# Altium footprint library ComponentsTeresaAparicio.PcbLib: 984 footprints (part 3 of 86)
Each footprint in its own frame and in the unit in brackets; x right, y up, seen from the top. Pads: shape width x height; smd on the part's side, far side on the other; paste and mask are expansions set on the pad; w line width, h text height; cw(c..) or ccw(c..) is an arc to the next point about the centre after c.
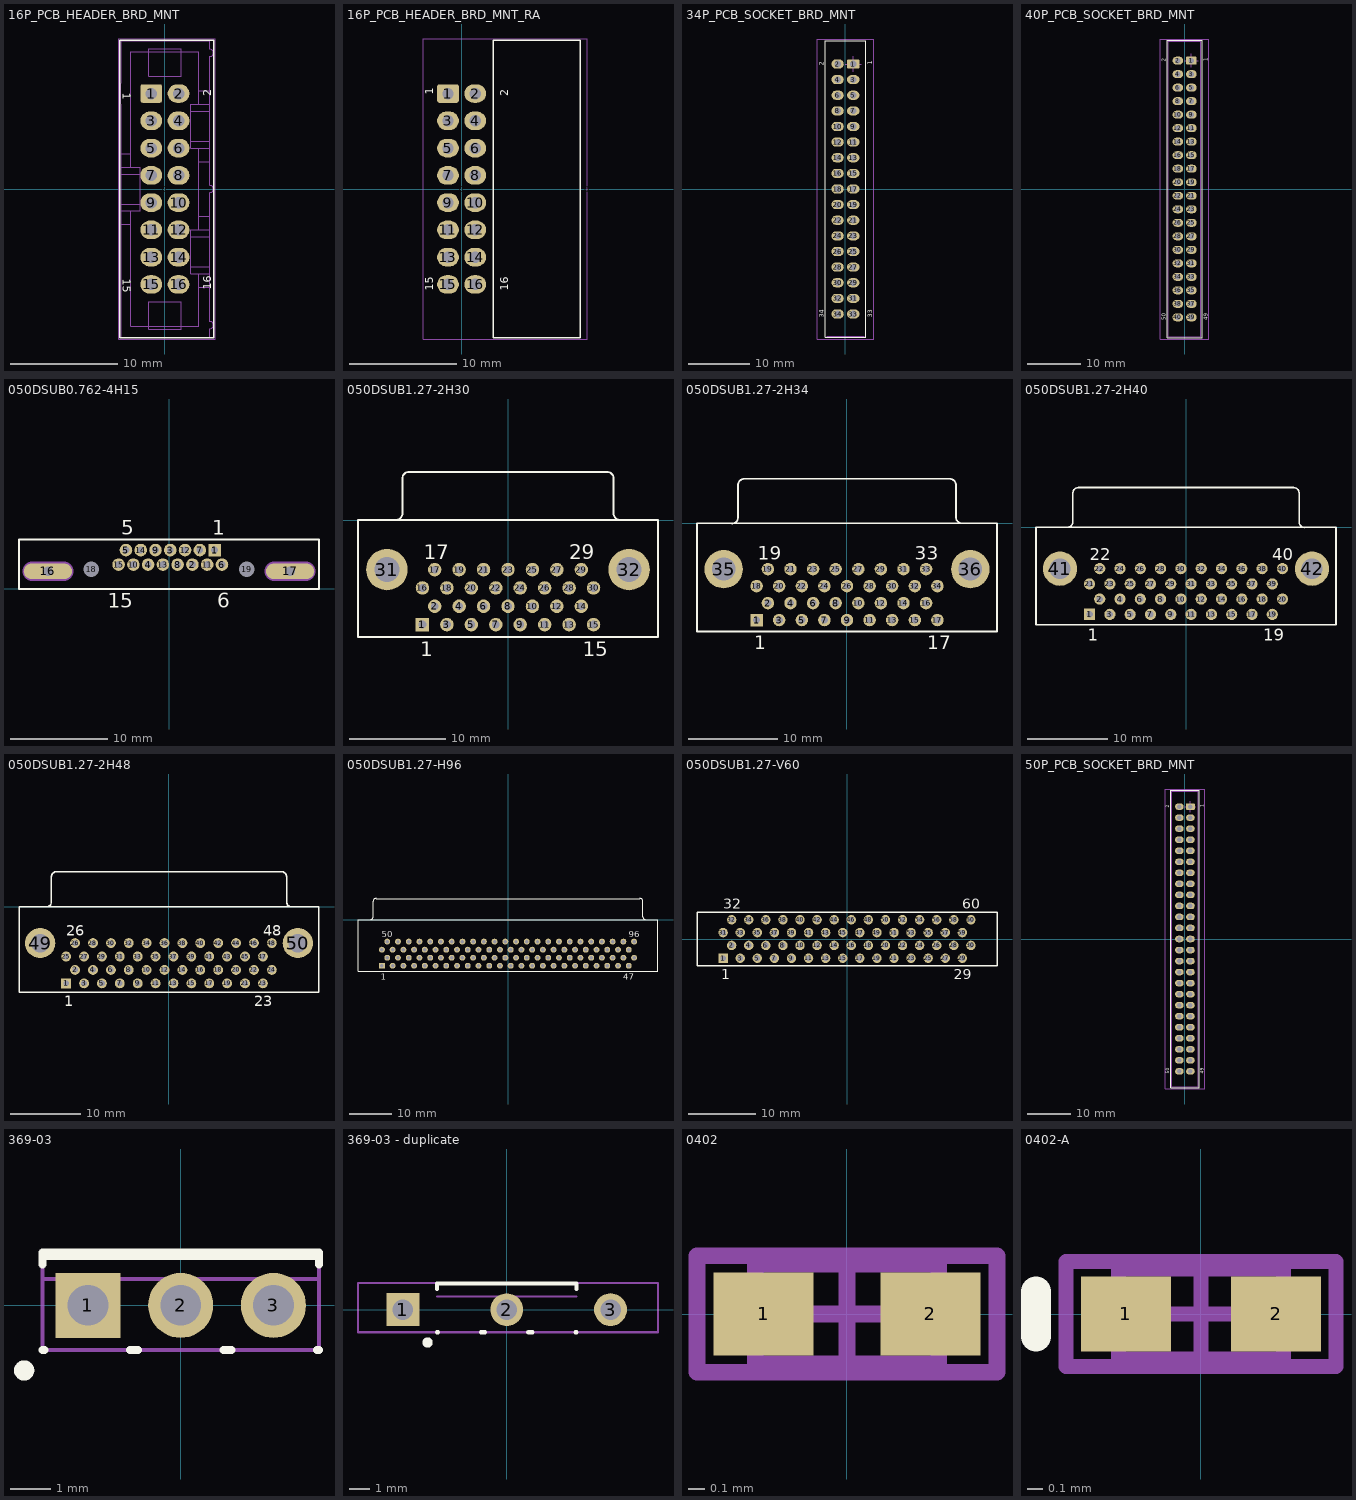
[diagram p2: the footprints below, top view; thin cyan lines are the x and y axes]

## 16P_PCB_HEADER_BRD_MNT [mil] "HEADER BRD MNT 16POS 2.54MM"
height 390
pads (17):
  round 40 on Mech14: 0(0,0)
  rrect25% 80x68 hole 42: 1(-50,350)
  oval 80x68 hole 42: 2(50,350) 3(-50,250) 4(50,250) 5(-50,150) 6(50,150) 7(-50,50) 8(50,50) 9(-50,-50) 10(50,-50) 11(-50,-150) 12(50,-150) 13(-50,-250) 14(50,-250) 15(-50,-350) 16(50,-350)
Top Overlay:
  lines w5: -165,-545 -165,545 180,545 180,-545 -165,-545
  text "2" at 170,340 h30
  text "1" at -155,353.57 h30
  text "16" at 170,-370.28 h30
  text "15" at -155,-329 h30
Mechanical 13:
  drawing of 242 lines, arcs and shapes, not listed
Mechanical 14:
  lines w3: -170,-550 -170,550 185,550 185,-550 -170,-550
3D body: height 390, standoff -120, extent -161.99,-543.99 178.01,544.01

## 16P_PCB_HEADER_BRD_MNT_RA [mil] "HEADER BRD MNT R/A 16POS 2.54MM"
height 338
pads (18):
  round 40 on Mech14: 0(0,0) 0(460,0)
  rrect25% 80x68 hole 42: 1(-50,350)
  oval 80x68 hole 42: 2(50,350) 3(-50,250) 4(50,250) 5(-50,150) 6(50,150) 7(-50,50) 8(50,50) 9(-50,-50) 10(50,-50) 11(-50,-150) 12(50,-150) 13(-50,-250) 14(50,-250) 15(-50,-350) 16(50,-350)
Top Overlay:
  lines w5: 115,-545 435,-545 435,545 115,545 115,-545
  text "15" at -105,-373 h30
  text "16" at 170,-373 h30
  text "1" at -105,345 h30
  text "2" at 170,340 h30
Mechanical 14:
  lines w3: -140,-550 460,-550 460,550 -140,550 -140,-550
3D body: height 340, standoff -112, extent -62.24,-543.99 440.01,544.01

## 34P_PCB_SOCKET_BRD_MNT [mm] "SOCKET BRD MNT 34POS 2.54MM"
height 10.8
pads (34):
  rrect25% 2x1.5 hole 1.067: 1(1.27,20.32)
  oval 2x1.5 hole 1.067: 2(-1.27,20.32) 3(1.27,17.78) 4(-1.27,17.78) 5(1.27,15.24) 6(-1.27,15.24) 7(1.27,12.7) 8(-1.27,12.7) 9(1.27,10.16) 10(-1.27,10.16) 11(1.27,7.62) 12(-1.27,7.62) 13(1.27,5.08) 14(-1.27,5.08) 15(1.27,2.54) 16(-1.27,2.54) 17(1.27,0) 18(-1.27,0) 19(1.27,-2.54) 20(-1.27,-2.54) 21(1.27,-5.08) 22(-1.27,-5.08) 23(1.27,-7.62) 24(-1.27,-7.62) 25(1.27,-10.16) 26(-1.27,-10.16) 27(1.27,-12.7) 28(-1.27,-12.7) 29(1.27,-15.24) 30(-1.27,-15.24) 31(1.27,-17.78) 32(-1.27,-17.78) 33(1.27,-20.32) 34(-1.27,-20.32)
Top Overlay:
  lines w0.127: -3.302,-24.13 -3.302,24.13 3.302,24.13 3.302,-24.13 -3.302,-24.13
  text "1" at 4.318,20.193 h0.76
  text "2" at -3.556,20.066 h0.76
  text "33" at 4.318,-20.904 h0.76
  text "34" at -3.556,-20.904 h0.76
Mechanical 13:
  lines w0.076: -3.05,-23.92 3.05,-23.92
Mechanical 14:
  lines w0.076: 0,20.32 2.54,20.32 ; 1.27,19.05 1.27,21.59 ; -4.572,-24.384 -4.572,24.384 4.572,24.384 4.572,-24.384 -4.572,-24.384
3D body: height 10.8, standoff -2.8, extent -3.05,-23.925 4.05,23.915

## 40P_PCB_SOCKET_BRD_MNT [mm] "SOCKET BRD MNT 40POS 2.54MM"
height 10.8
pads (40):
  rrect25% 2x1.5 hole 1.067: 1(1.27,24.13)
  oval 2x1.5 hole 1.067: 2(-1.27,24.13) 3(1.27,21.59) 4(-1.27,21.59) 5(1.27,19.05) 6(-1.27,19.05) 7(1.27,16.51) 8(-1.27,16.51) 9(1.27,13.97) 10(-1.27,13.97) 11(1.27,11.43) 12(-1.27,11.43) 13(1.27,8.89) 14(-1.27,8.89) 15(1.27,6.35) 16(-1.27,6.35) 17(1.27,3.81) 18(-1.27,3.81) 19(1.27,1.27) 20(-1.27,1.27) 21(1.27,-1.27) 22(-1.27,-1.27) 23(1.27,-3.81) 24(-1.27,-3.81) 25(1.27,-6.35) 26(-1.27,-6.35) 27(1.27,-8.89) 28(-1.27,-8.89) 29(1.27,-11.43) 30(-1.27,-11.43) 31(1.27,-13.97) 32(-1.27,-13.97) 33(1.27,-16.51) 34(-1.27,-16.51) 35(1.27,-19.05) 36(-1.27,-19.05) 37(1.27,-21.59) 38(-1.27,-21.59) 39(1.27,-24.13) 40(-1.27,-24.13)
Top Overlay:
  lines w0.127: -3.302,-27.94 -3.302,27.94 3.302,27.94 3.302,-27.94 -3.302,-27.94
  text "50" at -3.556,-24.714 h0.76
  text "49" at 4.318,-24.714 h0.76
  text "2" at -3.556,23.876 h0.76
  text "1" at 4.318,24.003 h0.76
Mechanical 13:
  lines w0.076: -3.05,-27.73 3.05,-27.73 3.05,27.73 -3.05,27.73 -3.05,-27.73
Mechanical 14:
  lines w0.076: 0,24.13 2.54,24.13 ; 1.27,22.86 1.27,25.4 ; -4.572,-28.194 -4.572,28.194 4.572,28.194 4.572,-28.194 -4.572,-28.194
3D body: height 10.8, standoff -2.54, extent -3.05,-27.73 4.05,27.73

## 050DSUB0.762-4H15 [mm] "Connector; D Subminiature; 15 Position; Right Angle; Pitch 0.762 mm"
height 12.65
pads (19):
  rect 1.3x1.3 hole 0.7: 1(4.703,4)
  round 1.3 hole 0.7: 2(2.417,2.5) 3(0.131,4) 4(-2.155,2.5) 5(-4.441,4) 6(5.465,2.5) 7(3.179,4) 8(0.893,2.5) 9(-1.393,4) 10(-3.679,2.5) 11(3.941,2.5) 12(1.655,4) 13(-0.631,2.5) 14(-2.917,4) 15(-5.203,2.5)
  oval 5x1.6 hole 1: 16(-12.495,1.8) 17(12.495,1.8)
  round 1.3 hole 1.6: 18(-8,2) 19(8,2)
Top Overlay:
  lines w0.2: -15.48,0 15.48,0 15.48,5.1 -15.48,5.1 -15.48,0
  text "15" at -6.328,-1.975 h1.5
  text "6" at 4.965,-1.975 h1.5
  text "1" at 4.453,5.6 h1.5
  text "5" at -4.941,5.6 h1.5
Mechanical 1:
  lines w1.2: -14.12,1.8 -10.87,1.8 ; 10.87,1.8 14.12,1.8
  text "Alert PCB fab to slot details" at -15.505,-1.17 h0.3
  text "Slot 1.2x4.45mm, PTH" at -15.505,-1.67 h0.3
  text "Assign keep-out area to slot" at -15.505,-0.67 h0.3
  text "Mech 1 - Slot cut-out" at -15.505,-2.17 h0.3
  text "Mech 2 - Clearance, move to internal plane if present" at -15.505,-2.67 h0.3
Mechanical 2:
  lines w2.016: -14.12,1.8 -10.87,1.8 ; 10.87,1.8 14.12,1.8

## 050DSUB1.27-2H30 [mm] "Connector; D Subminiature; 30 Position; Right Angle; Pitch 1.27 mm"
height 8.1
pads (32):
  rect 1.4x1.4 hole 0.8: 1(-8.89,-10.87)
  round 1.4 hole 0.8: 2(-7.62,-8.965) 3(-6.35,-10.87) 4(-5.08,-8.965) 5(-3.81,-10.87) 6(-2.54,-8.965) 7(-1.27,-10.87) 8(0,-8.965) 9(1.27,-10.87) 10(2.54,-8.965) 11(3.81,-10.87) 12(5.08,-8.965) 13(6.35,-10.87) 14(7.62,-8.965) 15(8.89,-10.87) 16(-8.89,-7.06) 17(-7.62,-5.155) 18(-6.35,-7.06) 19(-5.08,-5.155) 20(-3.81,-7.06) 21(-2.54,-5.155) 22(-1.27,-7.06) 23(0,-5.155) 24(1.27,-7.06) 25(2.54,-5.155) 26(3.81,-7.06) 27(5.08,-5.155) 28(6.35,-7.06) 29(7.62,-5.155) 30(8.89,-7.06)
  round 4.3 hole 2.6: 31(-12.59,-5.155) 32(12.59,-5.155)
Top Overlay:
  lines w0.2: -11.67,0 ccw(c-11.67,0.695) -10.975,0.695 ; -10.975,0.715 -10.975,4.305 cw(c-10.28,4.305) -10.28,5 10.28,5 cw(c10.28,4.305) 10.975,4.305 ; 10.975,4.495 10.975,0.695 ccw(c11.67,0.695) 11.67,0 ; -15.59,-12.17 -15.59,0 15.59,0 15.59,-12.17 -15.59,-12.17
  text "17" at -8.745,-4.08 h1.5
  text "29" at 6.37,-4.08 h1.5
  text "1" at -9.14,-14.145 h1.5
  text "15" at 7.765,-14.145 h1.5

## 050DSUB1.27-2H34 [mm] "Connector; D Subminiature; 34 Position; Right Angle; Pitch 1.27 mm"
height 7.6
pads (36):
  rect 1.4x1.4 hole 0.8: 1(-10.16,-10.87)
  round 1.4 hole 0.8: 2(-8.89,-8.965) 3(-7.62,-10.87) 4(-6.35,-8.965) 5(-5.08,-10.87) 6(-3.81,-8.965) 7(-2.54,-10.87) 8(-1.27,-8.965) 9(0,-10.87) 10(1.27,-8.965) 11(2.54,-10.87) 12(3.81,-8.965) 13(5.08,-10.87) 14(6.35,-8.965) 15(7.62,-10.87) 16(8.89,-8.965) 17(10.16,-10.87) 18(-10.16,-7.06) 19(-8.89,-5.155) 20(-7.62,-7.06) 21(-6.35,-5.155) 22(-5.08,-7.06) 23(-3.81,-5.155) 24(-2.54,-7.06) 25(-1.27,-5.155) 26(0,-7.06) 27(1.27,-5.155) 28(2.54,-7.06) 29(3.81,-5.155) 30(5.08,-7.06) 31(6.35,-5.155) 32(7.62,-7.06) 33(8.89,-5.155) 34(10.16,-7.06)
  round 4.3 hole 2.6: 35(-13.86,-5.155) 36(13.86,-5.155)
Top Overlay:
  lines w0.2: -12.94,-0.02 ccw(c-12.94,0.675) -12.245,0.675 -12.245,4.305 cw(c-11.55,4.305) -11.55,5 11.5,5 ; 11.55,5 cw(c11.55,4.305) 12.245,4.305 12.245,0.695 ccw(c12.94,0.695) 12.94,0 ; -16.86,-12.17 16.86,-12.17 16.86,0 -16.86,0 -16.86,-12.17
  text "19" at -10.015,-4.08 h1.5
  text "33" at 7.64,-4.08 h1.5
  text "1" at -10.41,-14.145 h1.5
  text "17" at 9.035,-14.145 h1.5

## 050DSUB1.27-2H40 [mm] "Connector; D Subminiature; 40 Position; Right Angle; Pitch 1.27 mm"
height 8.1
pads (42):
  rect 1.4x1.4 hole 0.8: 1(-12.065,-10.87)
  round 1.4 hole 0.8: 2(-10.795,-8.965) 3(-9.525,-10.87) 4(-8.255,-8.965) 5(-6.985,-10.87) 6(-5.715,-8.965) 7(-4.445,-10.87) 8(-3.175,-8.965) 9(-1.905,-10.87) 10(-0.635,-8.965) 11(0.635,-10.87) 12(1.905,-8.965) 13(3.175,-10.87) 14(4.445,-8.965) 15(5.715,-10.87) 16(6.985,-8.965) 17(8.255,-10.87) 18(9.525,-8.965) 19(10.795,-10.87) 20(12.065,-8.965) 21(-12.065,-7.06) 22(-10.795,-5.155) 23(-9.525,-7.06) 24(-8.255,-5.155) 25(-6.985,-7.06) 26(-5.715,-5.155) 27(-4.445,-7.06) 28(-3.175,-5.155) 29(-1.905,-7.06) 30(-0.635,-5.155) 31(0.635,-7.06) 32(1.905,-5.155) 33(3.175,-7.06) 34(4.445,-5.155) 35(5.715,-7.06) 36(6.985,-5.155) 37(8.255,-7.06) 38(9.525,-5.155) 39(10.795,-7.06) 40(12.065,-5.155)
  round 4.3 hole 2.6: 41(-15.765,-5.155) 42(15.765,-5.155)
Top Overlay:
  lines w0.2: -14.845,0.02 ccw(c-14.845,0.715) -14.15,0.715 -14.15,4.305 cw(c-13.455,4.305) -13.455,5 ; -13.5,5 13.5,5 ; 13.455,5 cw(c13.455,4.305) 14.15,4.305 14.15,0.687 ccw(c14.845,0.687) 14.845,-0.008 ; -18.765,-12.17 -18.765,0 18.765,0 18.765,-12.17 -18.765,-12.17
  text "19" at 9.67,-14.145 h1.5
  text "1" at -12.315,-14.145 h1.5
  text "22" at -12.045,-4.08 h1.5
  text "40" at 10.815,-4.08 h1.5

## 050DSUB1.27-2H48 [mm] "Connector; D Subminiature; 48 Position; Right Angle; Pitch 1.27 mm"
height 7.6
pads (50):
  rect 1.4x1.4 hole 0.8: 1(-14.605,-10.87)
  round 1.4 hole 0.8: 2(-13.335,-8.965) 3(-12.065,-10.87) 4(-10.795,-8.965) 5(-9.525,-10.87) 6(-8.255,-8.965) 7(-6.985,-10.87) 8(-5.715,-8.965) 9(-4.445,-10.87) 10(-3.175,-8.965) 11(-1.905,-10.87) 12(-0.635,-8.965) 13(0.635,-10.87) 14(1.905,-8.965) 15(3.175,-10.87) 16(4.445,-8.965) 17(5.715,-10.87) 18(6.985,-8.965) 19(8.255,-10.87) 20(9.525,-8.965) 21(10.795,-10.87) 22(12.065,-8.965) 23(13.335,-10.87) 24(14.605,-8.965) 25(-14.605,-7.06) 26(-13.335,-5.155) 27(-12.065,-7.06) 28(-10.795,-5.155) 29(-9.525,-7.06) 30(-8.255,-5.155) 31(-6.985,-7.06) 32(-5.715,-5.155) 33(-4.445,-7.06) 34(-3.175,-5.155) 35(-1.905,-7.06) 36(-0.635,-5.155) 37(0.635,-7.06) 38(1.905,-5.155) 39(3.175,-7.06) 40(4.445,-5.155) 41(5.715,-7.06) 42(6.985,-5.155) 43(8.255,-7.06) 44(9.525,-5.155) 45(10.795,-7.06) 46(12.065,-5.155) 47(13.335,-7.06) 48(14.605,-5.155)
  round 4.3 hole 2.6: 49(-18.305,-5.155) 50(18.305,-5.155)
Top Overlay:
  lines w0.2: -17.385,0.002 ccw(c-17.385,0.697) -16.69,0.697 -16.69,4.305 cw(c-15.995,4.305) -15.995,5 ; -16,5 16,5 ; 15.995,5 cw(c15.995,4.305) 16.69,4.305 16.69,0.717 ccw(c17.385,0.717) 17.385,0.022 ; -21.305,-12.17 21.305,-12.17 21.305,0 -21.305,0 -21.305,-12.17
  text "26" at -14.585,-4.08 h1.5
  text "48" at 13.355,-4.08 h1.5
  text "1" at -14.855,-14.145 h1.5
  text "23" at 12.085,-14.145 h1.5

## 050DSUB1.27-H96 [mm] "Connector; D Subminiature; 96 Position; Right Angle; Pitch 1.27 mm"
height 7.5
pads (96):
  rect 1.4x1.4 hole 0.8: 1(-29.845,-10.915)
  round 1.4 hole 0.8: 2(-28.575,-9.01) 3(-27.305,-10.915) 4(-26.035,-9.01) 5(-24.765,-10.915) 6(-23.495,-9.01) 7(-22.225,-10.915) 8(-20.955,-9.01) 9(-19.685,-10.915) 10(-18.415,-9.01) 11(-17.145,-10.915) 12(-15.875,-9.01) 13(-14.605,-10.915) 14(-13.335,-9.01) 15(-12.065,-10.915) 16(-10.795,-9.01) 17(-9.525,-10.915) 18(-8.255,-9.01) 19(-6.985,-10.915) 20(-5.715,-9.01) 21(-4.445,-10.915) 22(-3.175,-9.01) 23(-1.905,-10.915) 24(-0.635,-9.01) 25(0.635,-10.915) 26(1.905,-9.01) 27(3.175,-10.915) 28(4.445,-9.01) 29(5.715,-10.915) 30(6.985,-9.01) 31(8.255,-10.915) 32(9.525,-9.01) 33(10.795,-10.915) 34(12.065,-9.01) 35(13.335,-10.915) 36(14.605,-9.01) 37(15.875,-10.915) 38(17.145,-9.01) 39(18.415,-10.915) 40(19.685,-9.01) 41(20.955,-10.915) 42(22.225,-9.01) 43(23.495,-10.915) 44(24.765,-9.01) 45(26.035,-10.915) 46(27.305,-9.01) 47(28.575,-10.915) 48(29.845,-9.01) 49(-29.845,-7.105) 50(-28.575,-5.2) 51(-27.305,-7.105) 52(-26.035,-5.2) 53(-24.765,-7.105) 54(-23.495,-5.2) 55(-22.225,-7.105) 56(-20.955,-5.2) 57(-19.685,-7.105) 58(-18.415,-5.2) 59(-17.145,-7.105) 60(-15.875,-5.2) 61(-14.605,-7.105) 62(-13.335,-5.2) 63(-12.065,-7.105) 64(-10.795,-5.2) 65(-9.525,-7.105) 66(-8.255,-5.2) 67(-6.985,-7.105) 68(-5.715,-5.2) 69(-4.445,-7.105) 70(-3.175,-5.2) 71(-1.905,-7.105) 72(-0.635,-5.2) 73(0.635,-7.105) 74(1.905,-5.2) 75(3.175,-7.105) 76(4.445,-5.2) 77(5.715,-7.105) 78(6.985,-5.2) 79(8.255,-7.105) 80(9.525,-5.2) 81(10.795,-7.105) 82(12.065,-5.2) 83(13.335,-7.105) 84(14.605,-5.2) 85(15.875,-7.105) 86(17.145,-5.2) 87(18.415,-7.105) 88(19.685,-5.2) 89(20.955,-7.105) 90(22.225,-5.2) 91(23.495,-7.105) 92(24.765,-5.2) 93(26.035,-7.105) 94(27.305,-5.2) 95(28.575,-7.105) 96(29.845,-5.2)
Top Overlay:
  lines w0.2: -32.625,0.005 ccw(c-32.625,0.7) -31.93,0.7 -31.93,4.33 cw(c-31.235,4.33) -31.235,5.025 ; -31.235,5 31.235,5 ; 31.235,5.025 cw(c31.235,4.33) 31.93,4.33 31.93,0.7 ccw(c32.625,0.7) 32.625,0.005 ; -35.5,-12.2 -35.5,0 35.5,0 35.5,-12.2 -35.5,-12.2
  text "96" at 28.595,-4.125 h1.5
  text "50" at -29.825,-4.125 h1.5
  text "1" at -30.095,-14.175 h1.5
  text "47" at 27.325,-14.175 h1.5

## 050DSUB1.27-V60 [mm] "Connector; D Subminiature; 60 Position; Vertical; Pitch 1.27 mm"
height 8
pads (60):
  rect 1.4x1.4 hole 0.8: 1(-18.415,-2.857)
  round 1.4 hole 0.8: 2(-17.145,-0.953) 3(-15.875,-2.857) 4(-14.605,-0.953) 5(-13.335,-2.857) 6(-12.065,-0.953) 7(-10.795,-2.857) 8(-9.525,-0.953) 9(-8.255,-2.857) 10(-6.985,-0.953) 11(-5.715,-2.857) 12(-4.445,-0.953) 13(-3.175,-2.857) 14(-1.905,-0.953) 15(-0.635,-2.857) 16(0.635,-0.953) 17(1.905,-2.857) 18(3.175,-0.953) 19(4.445,-2.857) 20(5.715,-0.953) 21(6.985,-2.857) 22(8.255,-0.953) 23(9.525,-2.857) 24(10.795,-0.953) 25(12.065,-2.857) 26(13.335,-0.953) 27(14.605,-2.857) 28(15.875,-0.953) 29(17.145,-2.857) 30(18.415,-0.953) 31(-18.415,0.953) 32(-17.145,2.857) 33(-15.875,0.953) 34(-14.605,2.857) 35(-13.335,0.953) 36(-12.065,2.857) 37(-10.795,0.953) 38(-9.525,2.857) 39(-8.255,0.953) 40(-6.985,2.857) 41(-5.715,0.953) 42(-4.445,2.857) 43(-3.175,0.953) 44(-1.905,2.857) 45(-0.635,0.953) 46(0.635,2.857) 47(1.905,0.953) 48(3.175,2.857) 49(4.445,0.953) 50(5.715,2.857) 51(6.985,0.953) 52(8.255,2.857) 53(9.525,0.953) 54(10.795,2.857) 55(12.065,0.953) 56(13.335,2.857) 57(14.605,0.953) 58(15.875,2.857) 59(17.145,0.953) 60(18.415,2.857)
Top Overlay:
  lines w0.2: -22.3,-4 -22.3,4 22.3,4 22.3,-4 -22.3,-4
  text "1" at -18.665,-5.975 h1.5
  text "29" at 15.895,-5.975 h1.5
  text "32" at -18.395,4.475 h1.5
  text "60" at 17.165,4.475 h1.5

## 50P_PCB_SOCKET_BRD_MNT [mm] "SOCKET BRD MNT 50POS 2.54MM"
height 10.8
pads (50):
  rrect25% 2x1.5 hole 1.067: 1(1.27,30.48)
  oval 2x1.5 hole 1.067: 2(-1.27,30.48) 3(1.27,27.94) 4(-1.27,27.94) 5(1.27,25.4) 6(-1.27,25.4) 7(1.27,22.86) 8(-1.27,22.86) 9(1.27,20.32) 10(-1.27,20.32) 11(1.27,17.78) 12(-1.27,17.78) 13(1.27,15.24) 14(-1.27,15.24) 15(1.27,12.7) 16(-1.27,12.7) 17(1.27,10.16) 18(-1.27,10.16) 19(1.27,7.62) 20(-1.27,7.62) 21(1.27,5.08) 22(-1.27,5.08) 23(1.27,2.54) 24(-1.27,2.54) 25(1.27,0) 26(-1.27,0) 27(1.27,-2.54) 28(-1.27,-2.54) 29(1.27,-5.08) 30(-1.27,-5.08) 31(1.27,-7.62) 32(-1.27,-7.62) 33(1.27,-10.16) 34(-1.27,-10.16) 35(1.27,-12.7) 36(-1.27,-12.7) 37(1.27,-15.24) 38(-1.27,-15.24) 39(1.27,-17.78) 40(-1.27,-17.78) 41(1.27,-20.32) 42(-1.27,-20.32) 43(1.27,-22.86) 44(-1.27,-22.86) 45(1.27,-25.4) 46(-1.27,-25.4) 47(1.27,-27.94) 48(-1.27,-27.94) 49(1.27,-30.48) 50(-1.27,-30.48)
Top Overlay:
  lines w0.127: -3.302,-34.29 3.302,-34.29 3.302,34.29 -3.302,34.29 -3.302,-34.29
  text "1" at 4.318,30.353 h0.76
  text "2" at -3.556,30.226 h0.76
  text "49" at 4.318,-31.064 h0.76
  text "50" at -3.556,-31.064 h0.76
Mechanical 13:
  lines w0.076: -3.05,-34.08 -3.05,34.08 3.05,34.08 3.05,-34.08 -3.05,-34.08
Mechanical 14:
  lines w0.076: 0,30.48 2.54,30.48 ; 1.27,29.21 1.27,31.75 ; -4.572,-34.544 4.572,-34.544 4.572,34.544 -4.572,34.544 -4.572,-34.544
3D body: height 10.8, standoff -2.8, extent -3.05,-34.085 4.05,34.075

## 369-03 [mm] "TO, Thru-Hole, Vertical, Heatsink Mounted; 3 In-Line Leads; Pitch 2.28 mm"
height 9.7
pads (3):
  rect 1.6x1.6 hole 1: 1(-2.28,0)
  round 1.6 hole 1: 2(0,0) 3(2.28,0)
Top Overlay:
  circle w0.25: c-3.85,-1.6 r0.125
  lines w0.2: -3.4,-1.1 -3.35,-1.1 ; -3.4,1 -3.4,1.3 3.4,1.3 3.4,1 ; -3.4,1.21 3.4,1.21 ; -1.25,-1.1 -1.05,-1.1 ; 1.05,-1.1 1.25,-1.1 ; 3.35,-1.1 3.4,-1.1
Mechanical 13:
  lines w0.1: -3.4,0.65 3.4,0.65 ; -3.4,-1.1 3.4,-1.1 3.4,1.3 -3.4,1.3 -3.4,-1.1
Mechanical 15:
  lines w0.1: -0.5,0 0.5,0 ; 0,-0.5 0,0.5
3D body: height 9.3, standoff 2.6, extent -3.45,-1.15 3.45,1.35
3D body: height 9.7, standoff 9.3, extent -3.399,0.651 3.399,1.299

## 369-03 - duplicate [mm] "TO, Thru-Hole, Vertical, Heatsink Mounted; 3 In-Line Leads; Pitch 2.28 mm"
height 9.7
pads (3):
  rect 1.6x1.6 hole 1: 1(-5.055,0)
  round 1.6 hole 1: 2(0,0) 3(5.055,0)
Top Overlay:
  circle w0.25: c-3.85,-1.6 r0.125
  lines w0.2: -3.4,-1.1 -3.35,-1.1 ; -3.4,1 -3.4,1.27 3.4,1.27 3.4,1 ; -1.25,-1.1 -1.05,-1.1 ; 1.05,-1.1 1.25,-1.1 ; 3.35,-1.1 3.4,-1.1
Mechanical 13:
  lines w0.1: -3.4,0.65 3.4,0.65 ; -7.239,-1.1 -7.239,1.3 7.366,1.3 7.366,-1.1 -7.239,-1.1
Mechanical 15:
  lines w0.1: -0.5,0 0.5,0 ; 0,-0.5 0,0.5
3D body: height 22.62, standoff -2, extent -7.874,-4.826 7.874,20.732

## 0402 [mm] "Chip Capacitor, Body 1.0x0.5mm, IPC High Density"
height 1.3
pads (2):
  rect 0.6x0.5 smd: 1(-0.5,0) 2(0.5,0)
Mechanical 13:
  lines w0.1: -0.55,-0.3 -0.55,0.3 0.55,0.3 0.55,-0.3 -0.55,-0.3
Mechanical 15:
  lines w0.1: -0.3,0 0.3,0 ; 0,-0.3 0,0.3 ; -0.9,-0.35 -0.9,0.35 0.9,0.35 0.9,-0.35 -0.9,-0.35
3D body: height 1.3, standoff 0, extent -0.55,-0.3 0.55,0.3

## 0402-A [mm] "Chip Inductor, Body 1.0x0.5mm, IPC High Density"
height 0.55
pads (2):
  rect 0.6x0.5 smd: 1(-0.5,0) 2(0.5,0)
Top Overlay:
  lines w0.2: -1.1,-0.15 -1.1,0.15
Mechanical 13:
  lines w0.1: -0.55,-0.3 0.55,-0.3 0.55,0.3 -0.55,0.3 -0.55,-0.3
Mechanical 15:
  lines w0.1: -0.3,0 0.3,0 ; 0,-0.3 0,0.3 ; -0.9,-0.35 0.9,-0.35 0.9,0.35 -0.9,0.35 -0.9,-0.35
3D body: height 0.55, standoff 0, extent -0.55,-0.3 0.55,0.3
